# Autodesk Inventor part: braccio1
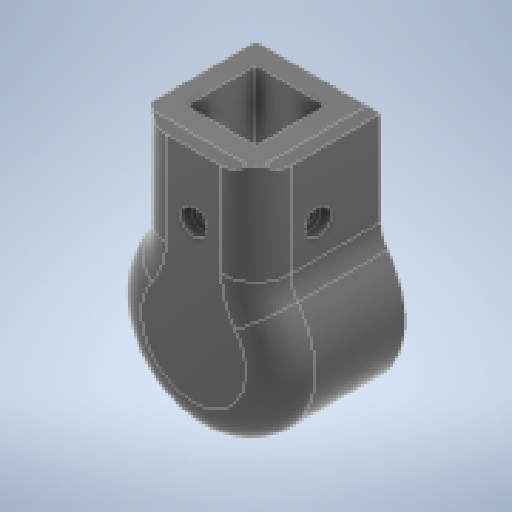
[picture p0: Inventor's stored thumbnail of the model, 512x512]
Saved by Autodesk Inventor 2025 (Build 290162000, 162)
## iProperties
Created: 2026-03
Part Number: braccio1
Material: Plastica ABS
Document SubType Name: Modeling
Designer: R5800u
Density: 1.06 g/cm^3
Appearance: Liscia - Nero
Author: R5800u
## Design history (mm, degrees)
sketch "Schizzo1"
  geometry: L1 (-2.646, 3)-(2.646, 3); C1 r 25 at (0, 0); A1 r 4 centre (0, 0) between (-2.646, 3) and (2.646, 3); 1 further point
  constraints: 2 centre point, 2 coincident, 2 end point, 2 point on circle, 1 horizontal
  dimensions: "d0" = 50 diameter of C1; "d1" = 8 diameter of A1; "d2" = 3 distance from line of point (0, 0) L1
extrude "Estrusione1" new body sketch "Schizzo1" stored distance "d3" = 36; taper "d4" = 0 deg
node "Piano di lavoro1"
sketch "Schizzo2"
  geometry: L1 (18, 18)-(-18, 18); L2 (-18, 18)-(-18, -18); L3 (-18, -18)-(18, -18); L4 (18, -18)-(18, 18); L5 (18, 18)-(-18, -18); L6 (-18, 18)-(18, -18); L7 (10, 10)-(-10, 10); L8 (-10, 10)-(-10, -10); L9 (-10, -10)-(10, -10); L10 (10, -10)-(10, 10); L11 (10, 10)-(-10, -10); L12 (-10, 10)-(10, -10); 1 further point
  constraints: 24 end point, 4 midpoint, 4 parallel, 2 horizontal, 2 perpendicular
  dimensions: "d6" = 36 distance of L3.end L2.end; "d7" = 36 distance of L2.end L1.end; "d8" = 20 distance of L9.end L8.end; "d9" = 20 distance of L8.end L7.end
extrude "Estrusione2" join sketch "Schizzo2" stored distance "d10" = 10; taper "d11" = 0 deg
sketch "Schizzo3"
  geometry: L1 (-10, 50)-(10, 50) reference; L2 (0, 50)-(0, 30); 1 further point
  constraints: 2 end point, 1 midpoint, 1 vertical
  dimensions: "d16" = 20 distance of L2.start L2.end
hole "Foro1" sketch "Schizzo3" at (0, 30) diameter "d17" = 4.3; stored, may be unused: countersink angle "d21" = 90 deg, drill point angle "d23" = 118 deg; dims "d18" = 6, "d19" = 7.5, "d20" = 3, "d22" = 8
pattern_circular "Serie circolare1" dims angle "d25" = 360 deg
chamfer "Smusso2" distance "d27" = 2; stored, may be unused: second distance "d28" = 2, angle "d29" = 45 deg
fillet "Raccordo2" dims "d30" = 10
fillet "Raccordo3" dims "d31" = 10
sketch "Schizzo4"
  geometry: A1 r 4 centre (0, 0) between (-2.646, 3) and (2.646, 3) reference; 3 further points
  constraints: 1 coincident, 3 other
extrude "Estrusione3" join sketch "Schizzo4" distance "d32" = 15; taper "d33" = 0 deg
sketch "Schizzo5"
  geometry: A1 r 15 centre (0, 0) between (-12, 9) and (12, 9) reference; 2 further points
  constraints: 1 coincident
hole "Foro2" sketch "Schizzo5" at (0, 0) diameter "d34" = 3.4; stored, may be unused: countersink angle "d38" = 90 deg, drill point angle "d40" = 118 deg; dims "d35" = 6, "d36" = 6, "d37" = 15, "d39" = 8
node "Solido1"
